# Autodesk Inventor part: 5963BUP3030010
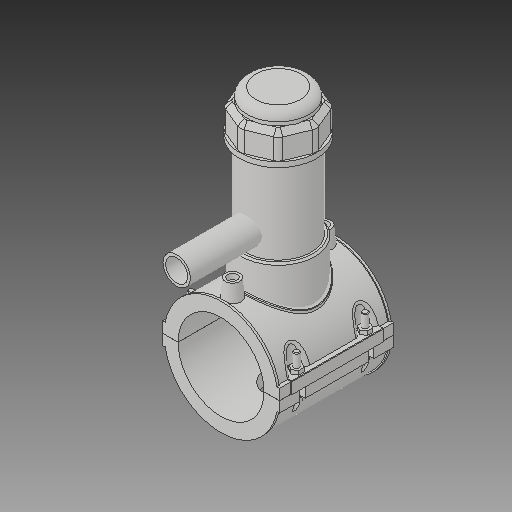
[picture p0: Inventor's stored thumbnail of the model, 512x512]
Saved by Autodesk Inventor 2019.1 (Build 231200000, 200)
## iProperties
Created: 2017-07
Part Number: 5963BUP3030010
Material: Generic
Description: PLASSON TAPPING SADDLE 3''IPS x 1''CTS
Document SubType Name: Modeling
Designer: KIM
Density: 1 g/cm^3
Appearance: Default
Author: KIM
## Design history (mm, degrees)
derived "5963BBP_5963BUP.ipt"
feature "Solid1::5963BBP_5963BUP.ipt"
feature "Solid2::5963BBP_5963BUP.ipt"
feature "Solid3::5963BBP_5963BUP.ipt"
tag "TaggingFeature1"
body "Solid1"
body "Solid2"
body "Solid3"
other parameters: "d0" = 88.7, "d2" = 120.904, "d3" = 22.175, "d4" = 118.11, "d5" = 0, "d6" = 0.1, "d8" = 0, "d19" = 6, "d20" = 6, "d21" = 70.866, "d23" = 0, "d24" = 35.433, "d26" = 0, "d27" = 3, "d28" = 3, "d29" = 3, "d30" = 29.56667, "d31" = 6, "d32" = 0, "d33" = 0, "d34" = 0.6, "d40" = 59.9612, "d41" = 79.83, "d43" = 0, "d45" = 0, "d47" = 128.521, "d70" = 15, "d72" = 0, "d73" = 6, "d75" = 5, "d76" = 0, "d77" = 4.435, "d78" = 74.35, "d79" = 15, "d80" = 47.244, "d82" = 5 deg, "d84" = 4, "d85" = 14, "d86" = 0, "d87" = 3, "d88" = 0, "d89" = 1, "d90" = 1, "d91" = 94.488, "d92" = 0, "d93" = 0.5, "d94" = 46.68421, "d96" = 117.6162, "d97" = 2.3622, "d98" = 0, "d102" = 0.887, "d120" = 140 deg, "d121" = 24.228, "d122" = 20 deg, "d123" = 230.62, "d124" = 69.186, "d126" = 0, "d143" = 91.361, "d145" = 20.46923, "d149" = 1.3305, "d150" = 22.51615, "d153" = 118.11, "d154" = 0, "d156" = 57.655, "d157" = 160 deg, "d159" = 5.322, "d161" = 1.3305, "d162" = 70.866, "d163" = 0, "d164" = 44.35, "d167" = 8.87, "d168" = 56.24878, "d170" = 3.2805, "d172" = 0, "d173" = 1, "d175" = 44.35, "d176" = 20 deg, "d177" = 6.209, "d178" = 26.61, "d180" = 0, "d183" = 10.644, "d184" = 4.9672, "d185" = 38.38575, "d186" = 38.38575, "d187" = 57.655, "d188" = 7.983, "d189" = 6.209, "d190" = 0, "d191" = 86.4825, "d193" = 6.9984, "d194" = 4.13385, "d195" = 90 deg, "d197" = 0, "d199" = 0, "d200" = 13.305, "d202" = 0, "d203" = 177.038, "d204" = 75.8385, "d205" = 55.881, "d206" = 67.8555, "d207" = 132.7785, "d208" = 138.08964, "d209" = 164.64534, "d210" = 68.6538, "d211" = 79.83, "d212" = 63.864, "d213" = 45.7191, "d216" = 0, "d217" = 8.87, "d218" = 8.87, "d219" = 1.774, "d222" = 88.7, "d224" = 0, "d225" = 65.024, "d226" = 28.45, "d227" = 22.76, "d228" = 104.902, "d230" = 5.322, "d_" = 88.7, "B_" = 120.904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
